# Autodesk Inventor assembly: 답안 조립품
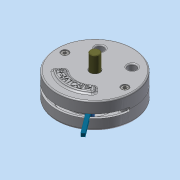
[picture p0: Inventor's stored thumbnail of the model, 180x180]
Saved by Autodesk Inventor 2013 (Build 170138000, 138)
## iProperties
Created: 2015-04
Part Number: 답안 조립품
Document SubType Name: Assembly
Designer: Administrator
Author: Administrator
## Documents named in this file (10)
- C:\Users\Administrator\Desktop\450406V1004\답안 조립품.iam
- C:\Users\Administrator\Desktop\450406V1004\M 10 x 35.ipt
- C:\Users\Administrator\Desktop\450406V1004\답안 본체.ipt
- C:\Users\Administrator\Desktop\450406V1004\덮개.ipt
- C:\Users\Administrator\Desktop\450406V1004\멈춤링.ipt
- C:\Users\Administrator\Desktop\450406V1004\베어링62_22.ipt
- C:\Users\Administrator\Desktop\450406V1004\슬라이더.ipt
- C:\Users\Administrator\Desktop\450406V1004\슬라이더2.ipt
- C:\Users\Administrator\Desktop\450406V1004\축.ipt
- C:\Users\Administrator\Desktop\450406V1004\평행핀.ipt
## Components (2 placed, 1 different names)
1. M 10 x 35:1
2. M 10 x 35:2
